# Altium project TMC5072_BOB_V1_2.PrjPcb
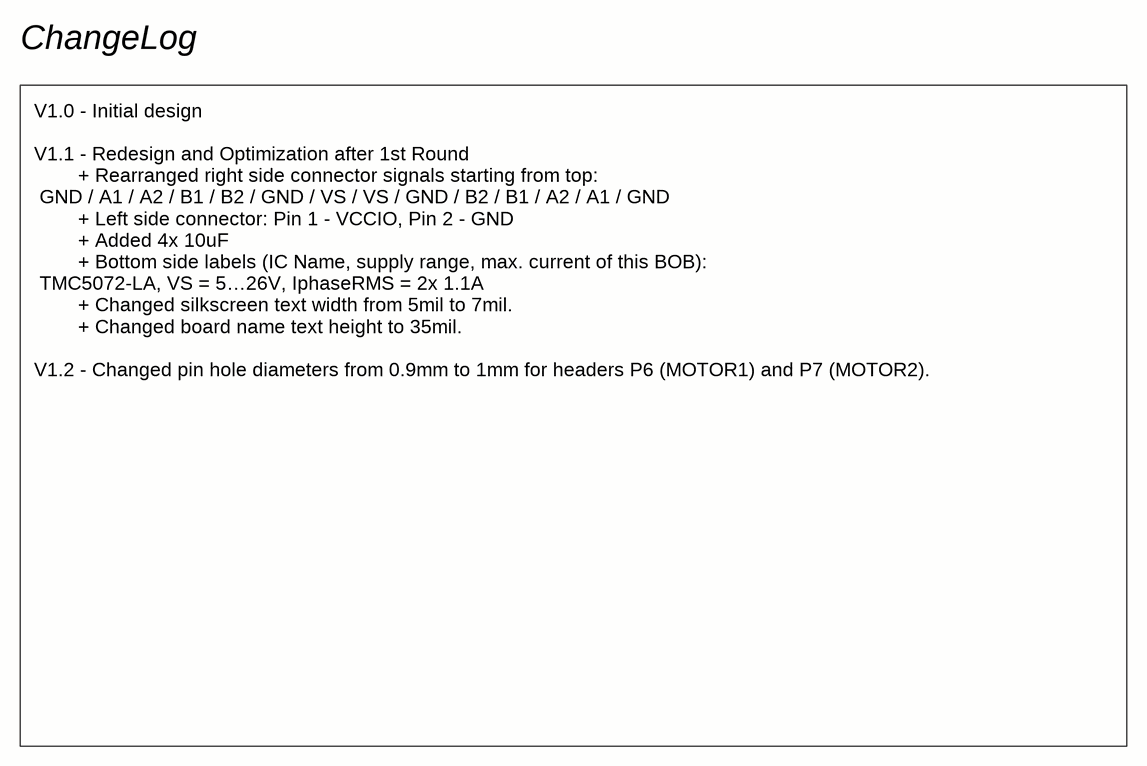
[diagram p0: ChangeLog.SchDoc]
BoardName: TMC5072-BOB; BoardVersion: 1.2; Chip: TMC5072-LA; IRMS: 2x 1.1A; VS: 5…26V
2 sheets, 32 parts. Net scope: global (net labels, ports and power ports of the same name join across sheets).
Board file: TMC5072_BOB_V1_2.PcbDoc
Sheets:
  ChangeLog.SchDoc
  TMC5072_BOB_V1_2.SchDoc

## Sheet ChangeLog.SchDoc
size A4

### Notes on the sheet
- ChangeLog
- V1.0 - Initial design
  V1.1 - Redesign and Optimization after 1st Round
  + Rearranged right side connector signals starting from top:
  GND / A1 / A2 / B1 / B2 / GND / VS / VS / GND / B2 / B1 / A2 / A1 / GND
  + Left side connector: Pin 1 - VCCIO, Pin 2 - GND
  + Added 4x 10uF
  + Bottom side labels (IC Name, supply range, max. current of this BOB):
  TMC5072-LA, VS = 5…26V, IphaseRMS = 2x 1.1A
  + Changed silkscreen text width from 5mil to 7mil.
  + Changed board name text height to 35mil.
  V1.2 - Changed pin hole diameters from 0.9mm to 1mm for headers P6 (MOTOR1) and P7 (MOTOR2).

## Sheet TMC5072_BOB_V1_2.SchDoc
size A4
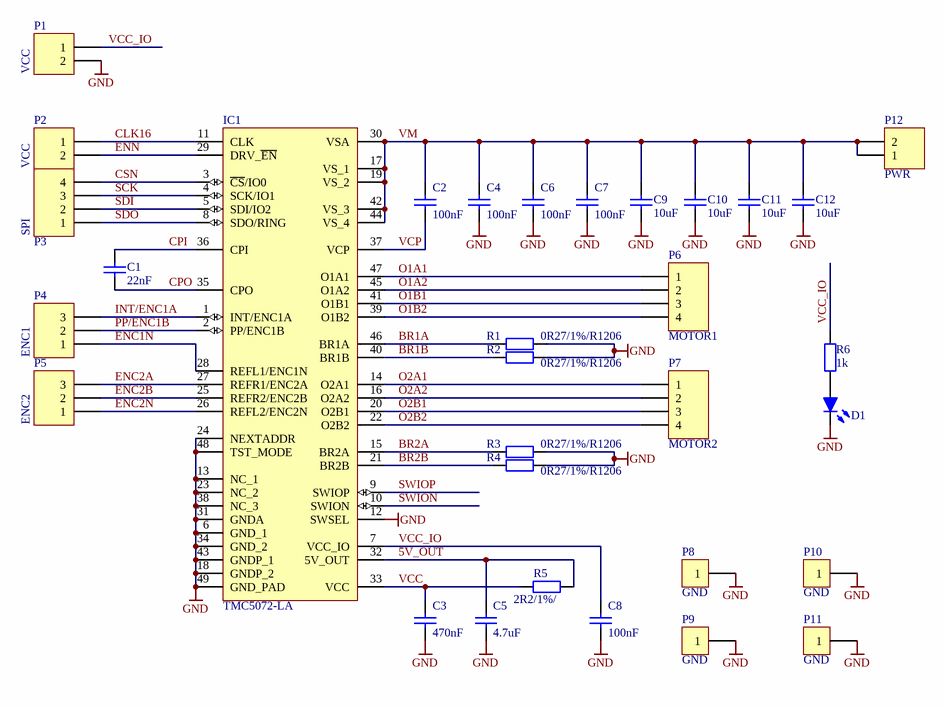
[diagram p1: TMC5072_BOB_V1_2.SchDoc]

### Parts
C1  22nF  [C0603]
C2  100nF  [C0603]
C3  470nF  [C0603]
C4  100nF  [C0603]
C5  4.7uF  [C0603]
C6  100nF  [C0603]
C7  100nF  [C0603]
C8  100nF  [C0603]
C9  10uF  [C1206]
C10  10uF  [C1206]
C11  10uF  [C1206]
C12  10uF  [C1206]
D1  LED, Blue, SMD, 20mA, 2.8V, 465 nm  [LED_0603]  (value not drawn)
IC1  TMC5072-LA  [TMC5072_QFN48_0.5_7.0X7.0]
P1  VCC  [2_PIN_THT]
P2  VCC  [2_PIN_THT]
P3  SPI  [4_PIN_THT]
P4  ENC1  [3_PIN_THT]
P5  ENC2  [3_PIN_THT]
P6  MOTOR1  [4_PIN_THT_1mm_hole]
P7  MOTOR2  [4_PIN_THT_1mm_hole]
P8  GND  [TH_PIN]
P9  GND  [TH_PIN]
P10  GND  [TH_PIN]
P11  GND  [TH_PIN]
P12  PWR  [2_PIN_THT]
R1  0R27/1%/R1206  [R1206]
R2  0R27/1%/R1206  [R1206]
R3  0R27/1%/R1206  [R1206]
R4  0R27/1%/R1206  [R1206]
R5  2R2/1%/  [R0603]
R6  1k  [R0603]

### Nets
GND: C3.2 C4.2 C5.2 C6.1 C7.1 C8.2 C9.2 C10.2 C11.2 C12.2 D1.2(K) IC1.6(GND_1) IC1.12(SWSEL) IC1.13(NC_1) IC1.18(GNDP_2) IC1.23(NC_2) IC1.24(NEXTADDR) IC1.31(GNDA) IC1.34(GND_2) IC1.38(NC_3) IC1.43(GNDP_1) IC1.48(TST_MODE) IC1.49(GND_PAD) P1.2 P8.1 P9.1 P10.1 P11.1 R1.1 R2.2 R3.1 R4.2
5V_OUT: C5.1 IC1.32(5V_OUT) R5.1
BR1A: IC1.46(BR1A) R1.2
BR1B: IC1.40(BR1B) R2.1
BR2A: IC1.15(BR2A) R3.2
BR2B: IC1.21(BR2B) R4.1
CLK16: IC1.11(CLK) P2.1
CPI: C1.2 IC1.36(CPI)
CPO: C1.1 IC1.35(CPO)
CSN: IC1.3(~{CS}/IO0) P3.4
ENC1N: IC1.28(REFL1/ENC1N) P4.1
ENC2A: IC1.27(REFR1/ENC2A) P5.3
ENC2B: IC1.25(REFR2/ENC2B) P5.2
ENC2N: IC1.26(REFL2/ENC2N) P5.1
ENN: IC1.29(DRV_~{EN}) P2.2
INT/ENC1A: IC1.1(INT/ENC1A) P4.3
O1A1: IC1.47(O1A1) P6.1
O1A2: IC1.45(O1A2) P6.2
O1B1: IC1.41(O1B1) P6.3
O1B2: IC1.39(O1B2) P6.4
O2A1: IC1.14(O2A1) P7.1
O2A2: IC1.16(O2A2) P7.2
O2B1: IC1.20(O2B1) P7.3
O2B2: IC1.22(O2B2) P7.4
PP/ENC1B: IC1.2(PP/ENC1B) P4.2
SCK: IC1.4(SCK/IO1) P3.3
SDI: IC1.5(SDI/IO2) P3.2
SDO: IC1.8(SDO/RING) P3.1
SWION: IC1.10(SWION)
SWIOP: IC1.9(SWIOP)
VCC: C3.1 IC1.33(VCC) R5.2
VCC_IO: C8.1 IC1.7(VCC_IO) P1.1 R6.1
VCP: C2.2 IC1.37(VCP)
VM: C2.1 C4.1 C6.2 C7.2 C9.1 C10.1 C11.1 C12.1 IC1.17(VS_1) IC1.19(VS_2) IC1.30(VSA) IC1.42(VS_3) IC1.44(VS_4) P12.1 P12.2
NetD1_1: D1.1(A) R6.2

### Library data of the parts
C1 = Capacitor: Ceramic capacitor; MPN: MC0603B223K500CT; Type: MLCC; Voltage rating: 50V; ComponentLinknDescription: Datasheet; MF: Multicomp; Precision: 20%
C2 C4 C6 C7 = Capacitor: Ceramic capacitor; MPN: MC0603F104M500CT; Type: MLCC; Voltage rating: 50V; ComponentLinknDescription: Datasheet; MF: Multicomp; Precision: 20%
C3 = Capacitor: Ceramic capacitor; MPN: MC0603X474K160CT; Type: MLCC; Voltage rating: 16V; ComponentLinknDescription: Datasheet; MF: Multicomp; Precision: 10%
C5 = Capacitor: Ceramic capacitor; MPN: MC0603X475K100CT; Type: MLCC; Voltage rating: 10V; ComponentLinknDescription: Datasheet; MF: Multicomp; Precision: 10%
C8 = Capacitor: Ceramic capacitor; Manufacturer: Multicomp; MPN: MC0603F104M500CT; Type: MLCC; Voltage rating: 50V; ComponentLinknDescription: Datasheet; Precision: 20%
C9-C12 = 10 µF, 25 V, ± 10%, X5R, MC Series, 1206 [3216 Metric]: SMD Multilayer Ceramic Capacitor, 1206 [3216 Metric], 10 µF, 25 V, ± 10%, X5R, MC Series; MPN: MC1206X106K250CT; Type: MLCC; Voltage rating: 25V; ComponentLinknDescription: Datasheet; MF: MULTICOMP
D1 = LED, Blue, SMD, 20mA, 2.8V, 465 nm: MPN: LTST-C191TBKT-5A; MF: Lite-On
IC1 = TMC5072-LA: Dual low-noise operation controllerfor up to two 2-phase bipolar stepper motors, with SPI, Step/Dir, UART, QFN48(7x7); Geometry.Height: 0,9 mm; Ordercode - Distri#1: 1460-1142-1-ND; MF: TRINAMIC
P1 P2 P12 = Header 2: Header, 2-Pin; Fitted: Not fitted
P3 = Header 4: Header, 4-Pin; Fitted: Not fitted
P4 P5 = Header 3: Header, 3-Pin; Fitted: Not fitted
P6 P7 = Wire-To-Board Connector, 2.5 mm, 4 Contacts, Header, EH Series, Through Hole, 1 Rows: MPN: B4B-EH-A; MF: JST (JAPAN SOLDERLESS TERMINALS); Fitted: Not fitted
P8-P11 = PIN: Note: n.b; Fitted: Not fitted
R1-R4 = Resistor: MPN: RCWE1206R270FKEA; Precision: 1%; Voltage rating: *V; Temp coefficient: *ppm; Power rating: 0.5W; ComponentLinknDescription: Datasheet; Resistance: 0R27; MF: Vishay
R5 = Resistor: MPN: MC0063W060312R2; Precision: 1%; Voltage rating: *V; Temp coefficient: *ppm; Power rating: *mW; ComponentLinknDescription: Datasheet; Resistance: 2R2; MF: Multicomp
R6 = 1 kohm, 50 V, 0603 [1608 Metric], 63 mW, ± 1%, MC Series: MPN: MC0063W060311K; VoltageRating: 50V; Temp coefficient: *ppm; PowerRating: 63mW; MF: MULTICOMP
